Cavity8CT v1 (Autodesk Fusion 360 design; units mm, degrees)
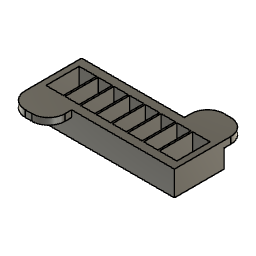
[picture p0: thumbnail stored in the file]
sketch "Sketch1" plane through (0, 0, 0) normal (0, 0, 1) x axis (1, 0, 0)
  line L1 (10.5, 0) -> (0, 0)
  line L2 (10.5, 20) -> (10.5, 0)
  line L3 (0, 20) -> (10.5, 20)
  line L4 (0, 0) -> (0, 20)
  line L5 (20, 0) -> (11.5, 0)
  line L6 (20, 20) -> (20, 0)
  line L7 (11.5, 20) -> (20, 20)
  line L8 (11.5, 0) -> (11.5, 20)
  line L9 (29.5, 0) -> (21, 0)
  line L10 (29.5, 20) -> (29.5, 0)
  line L11 (21, 20) -> (29.5, 20)
  line L12 (21, 0) -> (21, 20)
  line L13 (39, 0) -> (30.5, 0)
  line L14 (39, 20) -> (39, 0)
  line L15 (30.5, 20) -> (39, 20)
  line L16 (30.5, 0) -> (30.5, 20)
  line L17 (48.5, 0) -> (40, 0)
  line L18 (48.5, 20) -> (48.5, 0)
  line L19 (40, 20) -> (48.5, 20)
  line L20 (40, 0) -> (40, 20)
  line L21 (58, 0) -> (49.5, 0)
  line L22 (58, 20) -> (58, 0)
  line L23 (49.5, 20) -> (58, 20)
  line L24 (49.5, 0) -> (49.5, 20)
  line L25 (67.5, 0) -> (59, 0)
  line L26 (67.5, 20) -> (67.5, 0)
  line L27 (59, 20) -> (67.5, 20)
  line L28 (59, 0) -> (59, 20)
  line L29 (79, 0) -> (68.5, 0)
  line L30 (79, 20) -> (79, 0)
  line L31 (68.5, 20) -> (79, 20)
  line L32 (68.5, 0) -> (68.5, 20)
  line L33 (82.5, -5) -> (-3.5, -5)
  line L34 (82.5, 25) -> (82.5, -5)
  line L35 (-3.5, 25) -> (82.5, 25)
  line L36 (-3.5, -5) -> (-3.5, 25)
  point P1 (0, 0)
  point P2 (0, 0)
  point P3 (10.5, 0)
  point P5 (0, 20)
  point P6 (11.5, 0)
  point P7 (20, 0)
  point P10 (21, 0)
  point P11 (29.5, 0)
  point P13 (21, 20)
  point P14 (30.5, 0)
  point P15 (39, 0)
  point P17 (30.5, 20)
  point P18 (40, 0)
  point P19 (48.5, 0)
  point P21 (40, 20)
  point P22 (49.5, 0)
  point P23 (58, 0)
  point P25 (49.5, 20)
  point P26 (59, 0)
  point P27 (67.5, 0)
  point P29 (59, 20)
  point P30 (68.5, 0)
  point P31 (79, 0)
  point P33 (68.5, 20)
  horizontal L1
  vertical L2
  horizontal L3
  vertical L4
  coincident P1 P2
  horizontal L5
  vertical L6
  horizontal L7
  vertical L8
  horizontal L9
  vertical L10
  horizontal L11
  vertical L12
  horizontal L13
  vertical L14
  horizontal L15
  vertical L16
  horizontal L17
  vertical L18
  horizontal L19
  vertical L20
  horizontal L21
  vertical L22
  horizontal L23
  vertical L24
  horizontal L25
  vertical L26
  horizontal L27
  vertical L28
  horizontal L29
  vertical L30
  horizontal L31
  vertical L32
  horizontal L33
  vertical L34
  horizontal L35
  vertical L36
  dimension "d1" distance P2 P3 = 10.5
  dimension "d2" distance P2 P5 = 20
  dimension "d3" distance P6 P7 = 8.5
  dimension "d4" distance P10 P11 = 8.5
  dimension "d5" distance P10 P13 = 20
  dimension "d6" distance P14 P15 = 8.5
  dimension "d7" distance P14 P17 = 20
  dimension "d8" distance P18 P19 = 8.5
  dimension "d9" distance P18 P21 = 20
  dimension "d10" distance P22 P23 = 8.5
  dimension "d11" distance P22 P25 = 20
  dimension "d12" distance P26 P27 = 8.5
  dimension "d13" distance P26 P29 = 20
  dimension "d14" distance P30 P31 = 10.5
  dimension "d15" distance P30 P33 = 20
  dimension "d16" distance L2 L8 = 1
  dimension "d17" distance L6 L12 = 1
  dimension "d18" distance L10 L16 = 1
  dimension "d19" distance L14 L20 = 1
  dimension "d20" distance L18 L24 = 1
  dimension "d21" distance L22 L28 = 1
  dimension "d22" distance L26 L32 = 1
  dimension "d23" distance L30 L34 = 3.5
  dimension "d24" distance L31 L35 = 5
  dimension "d25" distance L29 L33 = 5
  dimension "d26" distance L4 L36 = 3.5
extrude "Extrude1" new body sketch "Sketch1" against normal blind 15
sketch "Sketch2" plane through (68.5, 0, 0) normal (1, 0, 0) x axis (0, 1, 0)
  line L1 (0, 0) -> (20, 0)
  line L2 (0, -15) -> (0, 0)
  line L3 (20, -15) -> (0, -15)
  line L4 (20, 0) -> (20, -15)
  line L5 (0, -15) -> (20, -15)
  line L6 (0, -12) -> (0, -15)
  line L7 (20, -12) -> (0, -12)
  line L8 (20, -15) -> (20, -12)
  point P5 (20, -15)
  point P6 (20, -15)
  point P7 (0, -15)
  point P9 (20, -12)
  horizontal L5
  vertical L6
  horizontal L7
  vertical L8
  coincident P5 P6
  dimension "d29" distance P6 P7 = 20
  dimension "d30" distance P6 P9 = 3
extrude "Extrude2" cut sketch "Sketch2" profile of L2 L3 L4 L5 L6 L7 L8 against normal blind 60
sketch "Sketch3" plane through (0, -5, 0) normal (0, -1, 0) x axis (1, 0, 0)
  line L1 (-3.5, 0) -> (82.5, 0)
  line L2 (-3.5, -15) -> (-3.5, 0)
  line L3 (82.5, -15) -> (-3.5, -15)
  line L4 (82.5, 0) -> (82.5, -15)
  line L5 (20.5, 0) -> (-3.5, 0)
  line L6 (20.5, -4) -> (20.5, 0)
  line L7 (-3.5, -4) -> (20.5, -4)
  line L8 (-3.5, 0) -> (-3.5, -4)
  point P3 (-3.5, 0)
  point P6 (-3.5, 0)
  point P7 (20.5, 0)
  point P9 (-3.5, -4)
  horizontal L5
  vertical L6
  horizontal L7
  vertical L8
  coincident P3 P6
  dimension "d33" distance P6 P7 = 24
  dimension "d34" distance P6 P9 = 4
extrude "Extrude3" add sketch "Sketch3" profile of L1 L2 L5 L6 L7 L8 along normal blind 14
fillet "Fillet1" radius 10
sketch "Sketch4" plane through (0, 25, 0) normal (0, 1, 0) x axis (-1, 0, 0)
  line L1 (-82.5, 0) -> (3.5, 0)
  line L2 (-82.5, -15) -> (-82.5, 0)
  line L3 (3.5, -15) -> (-82.5, -15)
  line L4 (3.5, 0) -> (3.5, -15)
  line L5 (-58.5, 0) -> (-82.5, 0)
  line L6 (-58.5, -4) -> (-58.5, 0)
  line L7 (-82.5, -4) -> (-58.5, -4)
  line L8 (-82.5, 0) -> (-82.5, -4)
  point P3 (-82.5, 0)
  point P6 (-82.5, 0)
  point P7 (-58.5, 0)
  point P9 (-82.5, -4)
  horizontal L5
  vertical L6
  horizontal L7
  vertical L8
  coincident P3 P6
  dimension "d39" distance P6 P7 = 24
  dimension "d40" distance P6 P9 = 4
extrude "Extrude4" add sketch "Sketch4" profile of L1 L2 L5 L6 L7 L8 along normal blind 14
fillet "Fillet2" radius 10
